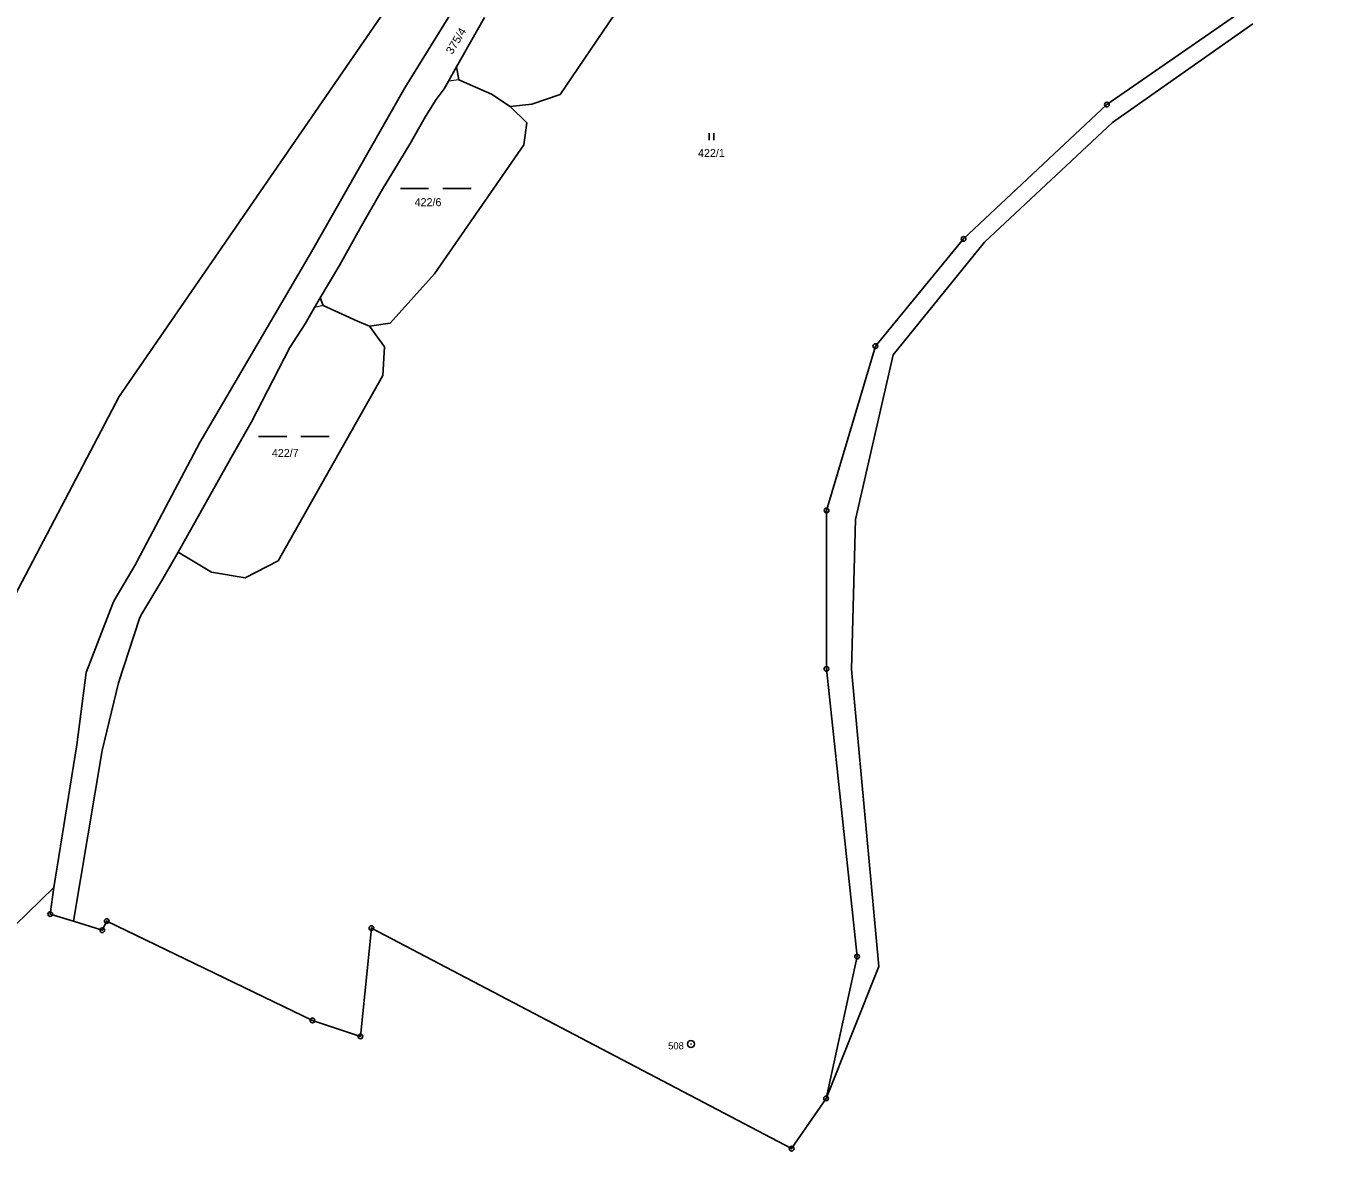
# Model space of a CAD drawing. Extents: x -885985 to -883535, y -1030025 to -1027941.
# Drawn here: x -884615.6 to -884339.7, y -1029321.4 to -1029082.6 of the extents above; entities that cross this region are included whole.
import ezdxf
from ezdxf.enums import TextEntityAlignment as Align

# ---------------------------------------------------------------- set-up
doc = ezdxf.new("R2010")
doc.units = 0
doc.header["$LTSCALE"] = 0.68
for name, color, linetype, lineweight in [('1', 7, 'Continuous', 25), ('3', 7, 'Continuous', 25), ('4', 7, 'Continuous', 13), ('8', 7, 'Continuous', 25)]:
    doc.layers.add(name, color=color, linetype=linetype, lineweight=lineweight)
doc.layers.add('2', color=7, linetype='Continuous')

msp = doc.modelspace()

# ---------------------------------------------------------------- linework, layer by layer
at = {"layer": '1'}
for p, q in [((-884516.49, -1029046.16), (-884595.79, -1029161.22)), ((-884535.09, -1029095.66), (-884510.06, -1029055.09)), ((-884481.63, -1029066.87), (-884502.09, -1029097.07)), ((-884339.7, -1029067.1), (-884386.02, -1029099.23)), ((-884524.11, -1029091.25), (-884518.18, -1029080.73)), ((-884384.8, -1029103.02), (-884355.02, -1029082.12)), ((-884525.8, -1029094.24), (-884524.11, -1029091.25)), ((-884523.63, -1029093.97), (-884524.11, -1029091.25)), ((-884554.95, -1029130.47), (-884535.09, -1029095.66)), ((-884528.48, -1029098.17), (-884526.74, -1029095.9)), ((-884526.74, -1029095.9), (-884525.8, -1029094.24)), ((-884516.68, -1029096.99), (-884523.63, -1029093.97)), ((-884530.7, -1029101.76), (-884528.48, -1029098.17)), ((-884512.75, -1029099.62), (-884516.68, -1029096.99)), ((-884502.09, -1029097.07), (-884508.14, -1029099.18)), ((-884534.03, -1029107.62), (-884530.7, -1029101.76)), ((-884508.14, -1029099.18), (-884512.75, -1029099.62)), ((-884512.75, -1029099.62), (-884509.21, -1029103.1)), ((-884386.02, -1029099.23), (-884416.45, -1029127.74)), ((-884509.21, -1029103.1), (-884509.81, -1029107.76)), ((-884412.01, -1029128.47), (-884384.8, -1029103.02)), ((-884539.88, -1029117.2), (-884534.03, -1029107.62)), ((-884509.81, -1029107.76), (-884528.8, -1029135.17)), ((-884544.29, -1029124.95), (-884539.88, -1029117.2)), ((-884548.93, -1029133.24), (-884544.29, -1029124.95)), ((-884416.45, -1029127.74), (-884435.19, -1029150.51)), ((-884431.41, -1029152.34), (-884412.01, -1029128.47)), ((-884578.61, -1029170.98), (-884554.95, -1029130.47)), ((-884548.93, -1029133.24), (-884553.05, -1029140.27)), ((-884538.22, -1029145.64), (-884528.8, -1029135.17)), ((-884553.05, -1029140.27), (-884554.26, -1029142.33)), ((-884552.43, -1029141.89), (-884553.05, -1029140.27)), ((-884554.26, -1029142.33), (-884556.28, -1029145.79)), ((-884545.15, -1029145.22), (-884552.43, -1029141.89)), ((-884559.49, -1029150.83), (-884556.28, -1029145.79)), ((-884545.15, -1029145.22), (-884542.62, -1029146.28)), ((-884542.62, -1029146.28), (-884538.22, -1029145.64)), ((-884542.62, -1029146.28), (-884539.41, -1029150.68)), ((-884567.76, -1029166.71), (-884559.49, -1029150.83)), ((-884539.41, -1029150.68), (-884539.78, -1029156.78)), ((-884435.19, -1029150.51), (-884445.55, -1029185.39)), ((-884439.39, -1029187.29), (-884431.41, -1029152.34)), ((-884539.78, -1029156.78), (-884562.01, -1029196.08)), ((-884595.79, -1029161.22), (-884672.21, -1029306.93)), ((-884572.07, -1029174.3), (-884567.76, -1029166.71)), ((-884591.95, -1029196.18), (-884578.61, -1029170.98)), ((-884572.07, -1029174.3), (-884583.27, -1029194.23)), ((-884445.55, -1029185.39), (-884445.57, -1029219.04)), ((-884440.24, -1029219.19), (-884439.39, -1029187.29)), ((-884583.27, -1029194.23), (-884586.49, -1029199.95)), ((-884576.19, -1029198.48), (-884583.27, -1029194.23)), ((-884596.81, -1029204.49), (-884592.22, -1029196.73)), ((-884592.22, -1029196.73), (-884591.95, -1029196.18)), ((-884562.01, -1029196.08), (-884569.04, -1029199.71)), ((-884591.15, -1029207.72), (-884586.49, -1029199.95)), ((-884569.04, -1029199.71), (-884576.19, -1029198.48)), ((-884602.76, -1029219.78), (-884597.1, -1029205.15)), ((-884597.1, -1029205.15), (-884596.81, -1029204.49)), ((-884595.9, -1029221.97), (-884591.45, -1029208.32)), ((-884591.45, -1029208.32), (-884591.15, -1029207.72)), ((-884604.75, -1029235.18), (-884602.76, -1029219.78)), ((-884445.57, -1029219.04), (-884439.08, -1029280.12)), ((-884434.43, -1029282.19), (-884440.24, -1029219.19)), ((-884599.38, -1029236.39), (-884595.9, -1029221.97)), ((-884609.66, -1029265.43), (-884604.75, -1029235.18)), ((-884605.48, -1029272.61), (-884599.38, -1029236.39)), ((-884609.66, -1029265.43), (-884620.71, -1029276.23)), ((-884610.4, -1029271.08), (-884609.66, -1029265.43)), ((-884605.48, -1029272.61), (-884610.4, -1029271.08)), ((-884599.37, -1029274.51), (-884605.48, -1029272.61)), ((-884598.41, -1029272.58), (-884599.37, -1029274.51)), ((-884554.72, -1029293.68), (-884598.41, -1029272.58)), ((-884542.2, -1029274.05), (-884544.53, -1029297.05)), ((-884452.96, -1029320.89), (-884542.2, -1029274.05)), ((-884439.08, -1029280.12), (-884445.65, -1029310.22)), ((-884445.65, -1029310.22), (-884434.43, -1029282.19)), ((-884544.53, -1029297.05), (-884554.72, -1029293.68)), ((-884445.65, -1029310.22), (-884452.96, -1029320.89))]:
    msp.add_line(p, q, dxfattribs=at)
at = {"layer": '3'}
for p, q in [((-884470.511, -1029106.8), (-884470.511, -1029105.3)), ((-884469.51, -1029106.8), (-884469.51, -1029105.3)), ((-884536.049, -1029117.02), (-884530.049, -1029117.02)), ((-884527.049, -1029117.02), (-884521.049, -1029117.02)), ((-884566.169, -1029169.68), (-884560.169, -1029169.68)), ((-884557.169, -1029169.68), (-884551.169, -1029169.68))]:
    msp.add_line(p, q, dxfattribs=at)
at = {"layer": '4'}
for p, q in [((-884523.63, -1029093.97), (-884525.8, -1029094.24)), ((-884552.43, -1029141.89), (-884554.26, -1029142.33))]:
    msp.add_line(p, q, dxfattribs=at)
at = {"layer": '8'}
for centre, radius in [((-884386.02, -1029099.2299), 0.5), ((-884386.02, -1029099.2299), 0.0303), ((-884416.45, -1029127.7399), 0.5), ((-884416.45, -1029127.7399), 0.0303), ((-884435.19, -1029150.5099), 0.5), ((-884435.19, -1029150.5099), 0.0303), ((-884445.55, -1029185.3899), 0.5), ((-884445.55, -1029185.3899), 0.0303), ((-884445.57, -1029219.0399), 0.5), ((-884445.57, -1029219.0399), 0.0303), ((-884610.4, -1029271.0799), 0.5), ((-884610.4, -1029271.0799), 0.0303), ((-884598.41, -1029272.5799), 0.5), ((-884598.41, -1029272.5799), 0.0303), ((-884599.37, -1029274.5099), 0.5), ((-884599.37, -1029274.5099), 0.0303), ((-884542.2, -1029274.0499), 0.5), ((-884542.2, -1029274.0499), 0.0303), ((-884439.08, -1029280.1199), 0.5), ((-884439.08, -1029280.1199), 0.0303), ((-884554.72, -1029293.6799), 0.5), ((-884554.72, -1029293.6799), 0.0303), ((-884544.53, -1029297.0499), 0.5), ((-884544.53, -1029297.0499), 0.0303), ((-884474.35, -1029298.6798), 0.75), ((-884474.35, -1029298.6798), 0.03), ((-884445.65, -1029310.2199), 0.5), ((-884445.65, -1029310.2199), 0.0303), ((-884452.96, -1029320.8899), 0.5), ((-884452.96, -1029320.8899), 0.0303)]:
    msp.add_circle(centre, radius, dxfattribs=at)

# ---------------------------------------------------------------- texts
at = {"layer": '2', "width": 1.05}
msp.add_text('375/4', height=1.7, rotation=59, dxfattribs=at).set_placement((-884525.045, -1029088.718))
at = {"layer": '2'}
for s, p in [('422/1', (-884470, -1029110.365)), ('422/6', (-884530.18, -1029120.805)), ('422/7', (-884560.49, -1029174.045))]:
    msp.add_text(s, height=1.7, dxfattribs=at).set_placement(p, align=Align.CENTER)
at = {"layer": '8'}
msp.add_text('508', height=1.5, dxfattribs=at).set_placement((-884475.849, -1029299.797), align=Align.RIGHT)

doc.saveas('drawing.dxf')
